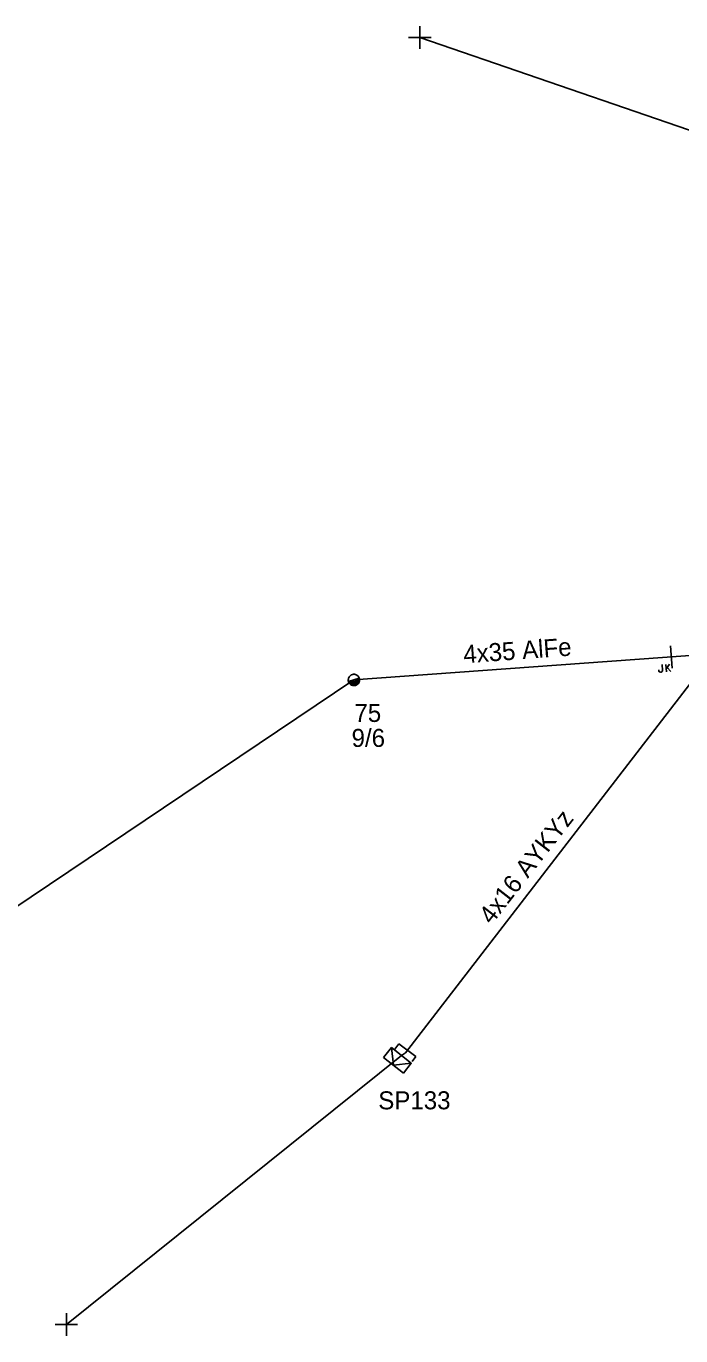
# Model space of a CAD drawing. Extents: x -748492 to -735633, y -1146251 to -1139940.
# Drawn here: x -742508.9 to -742472.5, y -1141310.1 to -1141237.4 of the extents above; entities that cross this region are included whole.
import ezdxf

# ---------------------------------------------------------------- set-up
doc = ezdxf.new("R2010")
doc.units = 0
for name, color, linetype in [('Vrstva 1', 7, 'Continuous'), ('Vrstva 12', 7, 'Continuous'), ('Vrstva 13', 7, 'Continuous'), ('Vrstva 14', 7, 'Continuous'), ('Vrstva 15', 7, 'Continuous'), ('Vrstva 18', 7, 'Continuous'), ('Vrstva 2', 7, 'Continuous'), ('Vrstva 31', 7, 'Continuous'), ('Vrstva 33', 7, 'Continuous'), ('Vrstva 34', 7, 'Continuous'), ('Vrstva 54', 7, 'Continuous'), ('Vrstva 55', 7, 'Continuous'), ('Vrstva 59', 7, 'Continuous'), ('Vrstva 9', 7, 'Continuous')]:
    doc.layers.add(name, color=color, linetype=linetype)

# ---------------------------------------------------------------- blocks, each defined once
blk = doc.blocks.new('NN440')
at = {"layer": 'Vrstva 2'}
for points in [[(0.63, 0), (0.63, 0.06), (0.62, 0.13), (0.6, 0.19), (0.58, 0.25), (0.55, 0.31), (0.51, 0.37), (0.47, 0.42), (0.42, 0.46), (0.37, 0.51), (0.32, 0.54), (0.26, 0.57), (0.2, 0.59), (0.13, 0.61), (0.07, 0.62), (0, 0.63), (-0.06, 0.62), (-0.13, 0.61), (-0.19, 0.59), (-0.26, 0.57), (-0.31, 0.54), (-0.37, 0.51), (-0.42, 0.46), (-0.47, 0.42), (-0.51, 0.37), (-0.54, 0.31), (-0.57, 0.25), (-0.6, 0.19), (-0.62, 0.13), (-0.63, 0.06), (-0.63, 0), (-0.63, -0.07), (-0.62, -0.14), (-0.6, -0.2), (-0.57, -0.26), (-0.54, -0.32), (-0.51, -0.37), (-0.47, -0.43), (-0.42, -0.47), (-0.37, -0.51), (-0.31, -0.55), (-0.26, -0.58), (-0.19, -0.6), (-0.13, -0.62), (-0.06, -0.63), (0, -0.63), (0.07, -0.63), (0.13, -0.62), (0.2, -0.6), (0.26, -0.58), (0.32, -0.55), (0.37, -0.51), (0.42, -0.47), (0.47, -0.43), (0.51, -0.37), (0.55, -0.32), (0.58, -0.26), (0.6, -0.2), (0.62, -0.14), (0.63, -0.07), (0.63, 0)], [(-0.63, 0), (0.63, 0)], [(-0.6, -0.18), (0.57, -0.18)], [(-0.51, -0.32), (0.5, -0.32)], [(-0.37, -0.47), (0.35, -0.47)]]:
    blk.add_lwpolyline(points, dxfattribs=at)
blk = doc.blocks.new('NN840')
at = {"layer": 'Vrstva 15'}
for points in [[(0.003, 0.619), (0.003, -0.631)], [(-0.745, -0.71), (-0.745, -0.66)], [(-0.73, -0.764), (-0.745, -0.71)], [(-0.538, -0.71), (-0.558, -0.764)], [(-0.538, -0.385), (-0.538, -0.71)], [(-0.332, -0.385), (-0.332, -0.798)], [(-0.332, -0.641), (-0.125, -0.385)], [(-0.263, -0.557), (-0.091, -0.798)], [(-0.657, -0.798), (-0.73, -0.764)], [(-0.627, -0.798), (-0.657, -0.798)], [(-0.558, -0.764), (-0.627, -0.798)]]:
    blk.add_lwpolyline(points, dxfattribs=at)
blk = doc.blocks.new('NN800')
at = {"layer": 'Vrstva 1'}
for points in [[(-0.442, 0.442), (0.442, -0.442)], [(-0.442, -0.442), (0.442, 0.442)]]:
    blk.add_lwpolyline(points, dxfattribs=at)
blk = doc.blocks.new('NN630')
at = {"layer": 'Vrstva 9'}
for points in [[(-0.003, -0.7), (-0.703, 0)], [(-0.703, -0.7), (-0.703, 0), (0.697, 0), (0.697, -0.7)], [(-0.703, -0.7), (0.697, -0.7)], [(-0.003, -0.7), (0.697, 0)]]:
    blk.add_lwpolyline(points, dxfattribs=at)
blk = doc.blocks.new('NN515')
at = {"layer": 'Vrstva 2'}
for points in [[(-0.59, 0.176), (0.591, 0.176)], [(-0.59, 0.176), (-0.59, -0.179)], [(0.591, 0.176), (0.591, -0.179)]]:
    blk.add_lwpolyline(points, dxfattribs=at)

msp = doc.modelspace()

# ---------------------------------------------------------------- linework, layer by layer
at = {"layer": 'Vrstva 1'}
msp.add_lwpolyline([(-742470.71, -1141272.25), (-742490.66, -1141273.69), (-742512.85, -1141288.6), (-742537.76, -1141302.69)], dxfattribs=at)
at = {"layer": 'Vrstva 54'}
msp.add_lwpolyline([(-742470.71, -1141272.25), (-742487.8, -1141294.4), (-742488.02, -1141294.55)], dxfattribs=at)
at = {"layer": 'Vrstva 59'}
for points in [[(-742454.13, -1141249.29), (-742487, -1141238)], [(-742488.02, -1141294.55), (-742506.63, -1141309.5)]]:
    msp.add_lwpolyline(points, dxfattribs=at)

# ---------------------------------------------------------------- block references
at = {"layer": 'Vrstva 13', "xscale": 0.49999999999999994, "yscale": 0.5000000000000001, "rotation": 16.742390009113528}
msp.add_blockref('NN440', (-742490.66, -1141273.69), dxfattribs=at)
at = {"layer": 'Vrstva 13', "rotation": -36.46899329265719}
msp.add_blockref('NN515', (-742487.8, -1141294.4), dxfattribs=at)
at = {"layer": 'Vrstva 18', "rotation": 4.128475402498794}
msp.add_blockref('NN840', (-742473.028, -1141272.417), dxfattribs=at)
at = {"layer": 'Vrstva 31', "rotation": -38.62056383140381}
msp.add_blockref('NN630', (-742488.02, -1141294.55), dxfattribs=at)
at = {"layer": 'Vrstva 34', "rotation": 45}
for p in [(-742487, -1141238), (-742506.63, -1141309.5)]:
    msp.add_blockref('NN800', p, dxfattribs=at)

# ---------------------------------------------------------------- texts
at = {"layer": 'Vrstva 12'}
msp.add_text('9/6', height=1, rotation=359.974, dxfattribs=at).set_placement((-742490.789, -1141277.411))
at = {"layer": 'Vrstva 14'}
msp.add_text('75', height=1, rotation=359.965, dxfattribs=at).set_placement((-742490.631, -1141276.023))
at = {"layer": 'Vrstva 2'}
msp.add_text('4x35 AlFe', height=1, rotation=4.128, dxfattribs=at).set_placement((-742484.546, -1141272.769))
at = {"layer": 'Vrstva 33'}
msp.add_text('SP133', height=1, rotation=0.04, dxfattribs=at).set_placement((-742489.306, -1141297.545))
at = {"layer": 'Vrstva 55'}
msp.add_text('4x16 AYKYz', height=1, rotation=52.104, dxfattribs=at).set_placement((-742483.009, -1141287.325))

doc.saveas('drawing.dxf')
